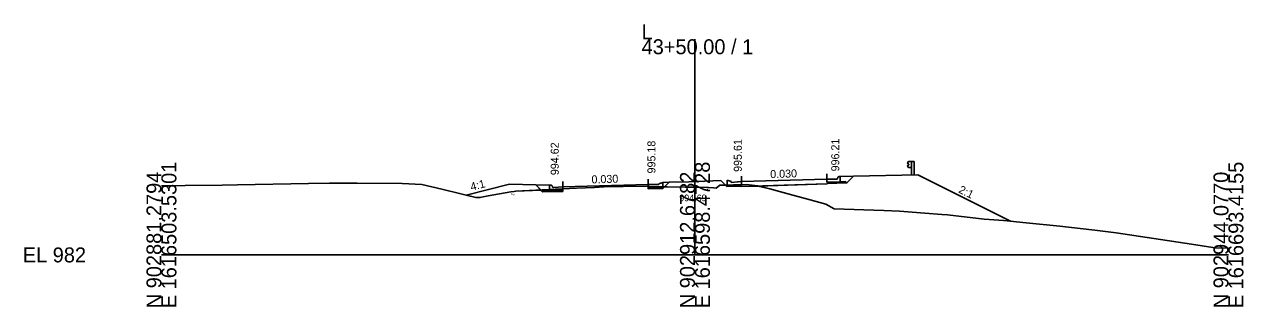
# Model space of a CAD drawing. Extents: x 1009 to 7438, y -1586 to 7964.
# Drawn here: x 4009.2 to 4237.7, y 1414 to 1467 of the extents above; entities that cross this region are included whole.
import ezdxf

# ---------------------------------------------------------------- set-up
doc = ezdxf.new("R2010")
doc.units = 0
for name, color, linetype in [('Exist Cross Section Cell', 7, 'Continuous'), ('Exist XS Center Line Elevation Label', 7, 'Continuous'), ('Exist XS Ground Line', 7, 'Continuous'), ('Prop XS Dump Level', 7, 'Continuous'), ('Prop XS Earthwork Shape', 7, 'Continuous'), ('Prop XS EOT Tick Mark', 7, 'Continuous'), ('Prop XS Finish Grade', 7, 'Continuous'), ('Prop XS Finish Grade CurbGutter', 7, 'Continuous'), ('Prop XS Finish Grade Earthwork', 7, 'Continuous'), ('Prop XS Finish Grade Pavement', 7, 'Continuous'), ('Prop XS Guardrail', 7, 'Continuous'), ('Prop XS Hydro Elevations', 7, 'Continuous'), ('Prop XS Pvmt Edge Slope', 7, 'Continuous'), ('Prop XS SE Text', 7, 'Continuous'), ('Prop XS Side Slope Text', 7, 'Continuous'), ('Prop XS Subgrade CurbGutter', 7, 'Continuous'), ('Prop XS Subgrade Earthwork', 7, 'Continuous')]:
    doc.layers.add(name, color=color, linetype=linetype)

msp = doc.modelspace()

# ---------------------------------------------------------------- linework, layer by layer
at = {"layer": 'Exist Cross Section Cell'}
for p, q in [((4134.89, 1423.73), (4134.89, 1464.16)), ((4034.89, 1423.73), (4134.89, 1423.73)), ((4134.89, 1423.73), (4234.89, 1423.73))]:
    msp.add_line(p, q, dxfattribs=at)
at = {"layer": 'Exist XS Ground Line'}
for p, q in [((4034.89, 1436.67), (4037.17, 1436.69)), ((4037.17, 1436.69), (4039.36, 1436.74)), ((4039.36, 1436.74), (4046.29, 1436.81)), ((4046.29, 1436.81), (4049.12, 1436.86)), ((4049.12, 1436.86), (4062.44, 1437.14)), ((4062.44, 1437.14), (4066.36, 1437.2)), ((4066.36, 1437.2), (4071.58, 1437.21)), ((4071.58, 1437.21), (4080.02, 1437.15)), ((4080.02, 1437.15), (4083.72, 1436.96)), ((4083.72, 1436.96), (4087.47, 1436.08)), ((4087.47, 1436.08), (4093.82, 1434.49)), ((4096.1, 1434.78), (4100.39, 1435.58)), ((4100.39, 1435.58), (4101, 1435.63)), ((4101, 1435.63), (4101.33, 1435.67)), ((4101.33, 1435.67), (4108.77, 1436.04)), ((4108.77, 1436.04), (4112.71, 1436.24)), ((4112.71, 1436.24), (4116.08, 1436.4)), ((4116.08, 1436.4), (4117.85, 1436.5)), ((4117.85, 1436.5), (4121.41, 1436.58)), ((4121.41, 1436.58), (4122.96, 1436.61)), ((4122.96, 1436.61), (4133.04, 1436.45)), ((4133.04, 1436.45), (4134.89, 1436.42)), ((4134.89, 1436.42), (4137.09, 1436.39)), ((4137.09, 1436.39), (4137.43, 1436.37)), ((4137.43, 1436.37), (4138.36, 1436.31)), ((4138.36, 1436.31), (4138.87, 1436.24)), ((4138.87, 1436.24), (4139.55, 1436.78)), ((4139.55, 1436.78), (4140.25, 1436.8)), ((4140.25, 1436.8), (4144.54, 1436.92)), ((4144.54, 1436.92), (4146.11, 1436.76)), ((4146.11, 1436.76), (4146.61, 1436.68)), ((4146.61, 1436.68), (4148.92, 1436.1)), ((4148.92, 1436.1), (4153.24, 1434.93)), ((4093.82, 1434.49), (4094.57, 1434.49)), ((4094.57, 1434.49), (4096.1, 1434.78)), ((4153.24, 1434.93), (4156.51, 1434.05)), ((4156.51, 1434.05), (4159.43, 1433.24)), ((4159.43, 1433.24), (4160.99, 1432.36)), ((4160.99, 1432.36), (4170.31, 1432.03)), ((4170.31, 1432.03), (4173.25, 1431.92)), ((4173.25, 1431.92), (4177.97, 1431.56)), ((4177.97, 1431.56), (4181.17, 1431.32)), ((4181.17, 1431.32), (4182.22, 1431.24)), ((4182.22, 1431.24), (4189.08, 1430.46)), ((4189.08, 1430.46), (4192.76, 1430.18)), ((4192.76, 1430.18), (4197, 1429.74)), ((4197, 1429.74), (4203.29, 1429.1)), ((4203.29, 1429.1), (4204.91, 1428.94)), ((4204.91, 1428.94), (4209.82, 1428.39)), ((4209.82, 1428.39), (4212.83, 1428)), ((4212.83, 1428), (4213.82, 1427.9)), ((4213.82, 1427.9), (4227.94, 1425.74)), ((4227.94, 1425.74), (4231.97, 1425.11)), ((4231.97, 1425.11), (4232.33, 1425.05)), ((4232.33, 1425.05), (4234.89, 1424.97))]:
    msp.add_line(p, q, dxfattribs=at)
at = {"layer": 'Prop XS Dump Level'}
for p, q in [((4143.64, 1437.47), (4159.64, 1437.95)), ((4143.64, 1437.47), (4159.64, 1437.95)), ((4110.14, 1436.47), (4126.14, 1436.95)), ((4110.14, 1436.47), (4126.14, 1436.95))]:
    msp.add_line(p, q, dxfattribs=at)
at = {"layer": 'Prop XS Earthwork Shape'}
for points in [[(4140.25, 1436.8), (4140.63, 1436.81), (4139.74, 1437.7), (4133.76, 1437.43), (4130.12, 1437.35), (4130.04, 1437.35), (4129.2, 1436.51), (4133.04, 1436.45), (4134.89, 1436.42), (4137.09, 1436.39), (4137.43, 1436.37), (4138.36, 1436.31), (4138.87, 1436.24), (4139.55, 1436.78)], [(4170.31, 1432.03), (4173.25, 1431.92), (4177.97, 1431.56), (4181.17, 1431.32), (4182.22, 1431.24), (4189.08, 1430.46), (4192.7, 1430.18), (4194.01, 1430.05), (4176.64, 1438.73), (4164.64, 1438.49), (4163.39, 1437.24), (4159.64, 1437.12), (4159.64, 1437.04), (4146.74, 1436.65), (4148.92, 1436.1), (4153.24, 1434.93), (4156.51, 1434.05), (4159.43, 1433.24), (4160.99, 1432.36)], [(4091.99, 1434.95), (4093.82, 1434.49), (4094.57, 1434.49), (4096.1, 1434.78), (4100.39, 1435.58), (4101, 1435.63), (4101.33, 1435.67), (4106.01, 1435.9), (4105.04, 1436.88), (4100.14, 1436.99)], [(4106.39, 1435.53), (4106.01, 1435.9), (4107.64, 1435.99), (4107.64, 1435.81), (4106.64, 1435.78)], [(4110.14, 1435.64), (4106.39, 1435.53), (4106.64, 1435.78), (4107.64, 1435.81), (4110.14, 1435.89)], [(4110.14, 1436.11), (4110.14, 1435.89), (4107.64, 1435.81), (4107.64, 1435.99), (4108.77, 1436.04)], [(4126.14, 1436.37), (4127.64, 1436.4), (4128.67, 1436.42), (4128.89, 1436.42), (4128.89, 1436.52), (4126.14, 1436.56)], [(4126.14, 1436.37), (4127.64, 1436.4), (4128.67, 1436.42), (4128.89, 1436.2), (4126.14, 1436.12)], [(4128.89, 1436.2), (4129.2, 1436.51), (4128.89, 1436.52), (4128.89, 1436.42), (4128.67, 1436.42)], [(4141.14, 1436.82), (4140.9, 1436.81), (4140.9, 1436.82), (4140.63, 1436.81), (4140.88, 1436.56)], [(4143.64, 1436.89), (4142.14, 1436.85), (4141.14, 1436.82), (4140.88, 1436.56), (4143.64, 1436.64), (4143.64, 1436.56), (4146.74, 1436.65), (4146.61, 1436.68), (4146.11, 1436.76), (4144.54, 1436.92)], [(4140.9, 1436.82), (4143.64, 1436.89), (4142.14, 1436.85), (4141.14, 1436.82), (4140.9, 1436.81)]]:
    msp.add_lwpolyline(points, close=True, dxfattribs=at)
at = {"layer": 'Prop XS EOT Tick Mark'}
for p, q in [((4126.14, 1436.95), (4126.14, 1437.95)), ((4143.64, 1437.47), (4143.64, 1438.47)), ((4159.64, 1437.95), (4159.64, 1438.95)), ((4110.14, 1436.47), (4110.14, 1437.47))]:
    msp.add_line(p, q, dxfattribs=at)
at = {"layer": 'Prop XS Finish Grade'}
for p, q in [((4162.14, 1438.43), (4164.64, 1438.49)), ((4107.64, 1436.83), (4105.04, 1436.88)), ((4128.89, 1437.33), (4130.12, 1437.35))]:
    msp.add_line(p, q, dxfattribs=at)
at = {"layer": 'Prop XS Finish Grade CurbGutter'}
for p, q in [((4141.65, 1437.5), (4140.9, 1437.75)), ((4141.65, 1437.33), (4141.65, 1437.5)), ((4143.64, 1437.47), (4141.65, 1437.33)), ((4143.64, 1437.47), (4142.89, 1437.42)), ((4159.64, 1437.95), (4161.39, 1437.94)), ((4161.39, 1437.94), (4161.52, 1437.96)), ((4161.52, 1437.96), (4161.61, 1438.05)), ((4161.61, 1438.05), (4161.68, 1438.3)), ((4161.68, 1438.3), (4161.77, 1438.39)), ((4161.89, 1438.43), (4161.77, 1438.39)), ((4162.14, 1438.43), (4161.89, 1438.43)), ((4107.64, 1436.83), (4107.89, 1436.83)), ((4107.89, 1436.83), (4108.02, 1436.8)), ((4108.11, 1436.71), (4108.02, 1436.8)), ((4108.18, 1436.46), (4108.11, 1436.71)), ((4108.27, 1436.37), (4108.18, 1436.46)), ((4108.39, 1436.35), (4108.27, 1436.37)), ((4110.14, 1436.47), (4108.39, 1436.35)), ((4126.14, 1436.95), (4128.14, 1436.91)), ((4128.14, 1437.08), (4128.89, 1437.33)), ((4128.14, 1436.91), (4128.14, 1437.08))]:
    msp.add_line(p, q, dxfattribs=at)
at = {"layer": 'Prop XS Finish Grade Earthwork'}
for p, q in [((4139.74, 1437.7), (4133.76, 1437.43)), ((4164.64, 1438.49), (4176.64, 1438.73)), ((4176.64, 1438.73), (4194.01, 1430.05)), ((4100.14, 1436.99), (4091.99, 1434.95)), ((4105.04, 1436.88), (4100.14, 1436.99)), ((4130.12, 1437.35), (4133.76, 1437.43))]:
    msp.add_line(p, q, dxfattribs=at)
at = {"layer": 'Prop XS Finish Grade Pavement'}
for p, q in [((4143.64, 1437.47), (4159.64, 1437.95)), ((4110.14, 1436.47), (4126.14, 1436.95))]:
    msp.add_line(p, q, dxfattribs=at)
at = {"layer": 'Prop XS Guardrail'}
for p, q in [((4174.7, 1441.05), (4174.67, 1440.99)), ((4174.67, 1440.99), (4174.7, 1440.93)), ((4174.7, 1440.44), (4174.67, 1440.38)), ((4174.67, 1440.38), (4174.7, 1440.32)), ((4174.99, 1441.25), (4174.7, 1441.05)), ((4174.7, 1440.93), (4174.99, 1440.73)), ((4174.99, 1440.64), (4174.7, 1440.44)), ((4174.7, 1440.32), (4174.99, 1440.12)), ((4175.49, 1441.25), (4174.99, 1441.25)), ((4174.99, 1440.73), (4174.99, 1440.64)), ((4174.99, 1440.12), (4175.49, 1440.12)), ((4175.99, 1441.25), (4175.49, 1441.25)), ((4175.49, 1441.25), (4175.49, 1438.75)), ((4175.99, 1438.75), (4175.99, 1441.25))]:
    msp.add_line(p, q, dxfattribs=at)
at = {"layer": 'Prop XS Pvmt Edge Slope'}
for p, q in [((4162.14, 1437.45), (4163.14, 1437.48)), ((4163.14, 1437.48), (4163.39, 1437.24)), ((4106.64, 1435.78), (4106.39, 1435.53)), ((4107.64, 1435.81), (4106.64, 1435.78)), ((4127.64, 1436.4), (4128.89, 1436.42)), ((4128.67, 1436.42), (4128.89, 1436.2)), ((4141.14, 1436.82), (4140.88, 1436.56)), ((4142.14, 1436.85), (4140.9, 1436.81))]:
    msp.add_line(p, q, dxfattribs=at)
at = {"layer": 'Prop XS Subgrade CurbGutter'}
for p, q in [((4140.9, 1436.81), (4140.9, 1437.75)), ((4143.64, 1437.47), (4143.64, 1436.89)), ((4159.64, 1437.95), (4159.64, 1437.37)), ((4162.14, 1437.45), (4162.14, 1438.43)), ((4107.64, 1435.81), (4107.64, 1436.83)), ((4110.14, 1435.89), (4107.64, 1435.81)), ((4110.14, 1436.47), (4110.14, 1435.89)), ((4126.14, 1436.95), (4126.14, 1436.37)), ((4126.14, 1436.37), (4127.64, 1436.4)), ((4128.89, 1436.42), (4128.89, 1437.33)), ((4143.64, 1436.89), (4142.14, 1436.85)), ((4159.64, 1437.37), (4162.14, 1437.45))]:
    msp.add_line(p, q, dxfattribs=at)
at = {"layer": 'Prop XS Subgrade Earthwork'}
for p, q in [((4140.88, 1436.56), (4139.74, 1437.7)), ((4163.39, 1437.24), (4164.64, 1438.49)), ((4106.39, 1435.53), (4105.04, 1436.88)), ((4110.14, 1435.64), (4106.39, 1435.53)), ((4110.14, 1435.64), (4110.14, 1436.11)), ((4126.14, 1436.12), (4126.14, 1436.56)), ((4126.14, 1436.12), (4128.89, 1436.2)), ((4128.89, 1436.2), (4130.04, 1437.35)), ((4143.64, 1436.64), (4140.88, 1436.56)), ((4143.64, 1436.56), (4159.64, 1437.04)), ((4143.64, 1436.56), (4143.64, 1436.64)), ((4159.64, 1437.12), (4163.39, 1437.24)), ((4159.64, 1437.04), (4159.64, 1437.12))]:
    msp.add_line(p, q, dxfattribs=at)

# ---------------------------------------------------------------- texts
at = {"layer": 'Exist Cross Section Cell'}
for s, p in [('L', (4124.89, 1464.16)), ('43+50.00 / 1', (4124.89, 1461.36)), ('EL 982', (4008.89, 1422.33))]:
    msp.add_text(s, height=2.8, dxfattribs=at).set_placement(p)
for s, p in [('E 1616503.5301', (4037.69, 1413.73)), ('E 1616598.4728', (4137.69, 1413.73)), ('E 1616693.4155', (4237.69, 1413.73)), ('N 902881.2794', (4034.89, 1413.73)), ('N 902912.6782', (4134.89, 1413.73)), ('N 902944.0770', (4234.89, 1413.73))]:
    msp.add_text(s, height=2.8, rotation=90, dxfattribs=at).set_placement(p)
at = {"layer": 'Exist XS Center Line Elevation Label'}
msp.add_text('994.69', height=1.25, dxfattribs=at).set_placement((4131.96, 1433.8))
at = {"layer": 'Prop XS Dump Level'}
for p in [(4100.38, 1434.95), (4137.09, 1435.76), (4137.09, 1435.76), (4137.09, 1435.76)]:
    msp.add_text('Eop', height=0.3, dxfattribs=at).set_placement(p)
at = {"layer": 'Prop XS Hydro Elevations'}
for s, p in [('994.62', (4109.36, 1438.69)), ('995.18', (4127.48, 1439.01)), ('995.61', (4143.67, 1439.3)), ('996.21', (4161.94, 1439.4))]:
    msp.add_text(s, height=1.5, rotation=90, dxfattribs=at).set_placement(p)
at = {"layer": 'Prop XS SE Text'}
for p in [(4149.02, 1438.13), (4115.52, 1437.13)]:
    msp.add_text('0.030', height=1.5, rotation=1.7184, dxfattribs=at).set_placement(p)
at = {"layer": 'Prop XS Side Slope Text'}
for s, rotation, p in [('4:1', 14.0362, (4093, 1435.75)), ('2:1', 333.4349, (4184.17, 1435.48))]:
    msp.add_text(s, height=1.5, rotation=rotation, dxfattribs=at).set_placement(p)

doc.saveas('drawing.dxf')
